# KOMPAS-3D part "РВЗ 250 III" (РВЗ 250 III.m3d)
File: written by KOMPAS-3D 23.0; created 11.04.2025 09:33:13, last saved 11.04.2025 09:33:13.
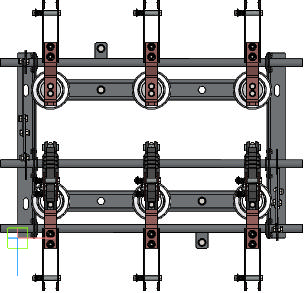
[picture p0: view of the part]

Document properties: Автор: pc; Полное имя файла: C:\Users\pc\Desktop\работа\РВЗ\3D макеты\РВЗ 250 III.m3d

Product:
- Body: Тело 1
    Масса: 0.01131
- Body: Тело 2
    Масса: 0.01131
- Body: Тело 3
    Масса: 1.849184
- Body: Тело 4
    Масса: 1.849184
- Body: Тело 5
    Масса: 0.052628
- Body: Тело 6
    Масса: 1.849184
- Part/product: РВЗ 250 III
    Масса: 5.622798

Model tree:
1. Операция без истории:1
2. Операция без истории:2
3. Операция без истории:3
4. Операция без истории:4
5. Операция без истории:5
6. Операция без истории:6
7. Поверхность без истории:1
8. Поверхность без истории:2
9. Поверхность без истории:3
10. Поверхность без истории:4
11. Поверхность без истории:5
12. Поверхность без истории:6
13. Поверхность без истории:7
14. Поверхность без истории:8
15. Поверхность без истории:9
16. Поверхность без истории:10
17. Поверхность без истории:11
18. Поверхность без истории:12
19. Поверхность без истории:13
20. Поверхность без истории:14
21. Поверхность без истории:15
22. Поверхность без истории:16
23. Поверхность без истории:17
24. Поверхность без истории:18
25. Поверхность без истории:19
26. Поверхность без истории:20
27. Поверхность без истории:21
28. Поверхность без истории:22
29. Поверхность без истории:23
30. Поверхность без истории:24
31. Поверхность без истории:25
32. Поверхность без истории:26
33. Поверхность без истории:27
34. Поверхность без истории:28
35. Поверхность без истории:29
36. Поверхность без истории:30
37. Поверхность без истории:31
38. Поверхность без истории:32
39. Поверхность без истории:33
40. Поверхность без истории:34
41. Поверхность без истории:35
42. Поверхность без истории:36
43. Поверхность без истории:37
44. Поверхность без истории:38
45. Поверхность без истории:39
46. Поверхность без истории:40
47. Поверхность без истории:41
48. Поверхность без истории:42
49. Поверхность без истории:43
50. Поверхность без истории:44
51. Поверхность без истории:45
52. Поверхность без истории:46
53. Поверхность без истории:47
54. Поверхность без истории:48
55. Поверхность без истории:49
56. Поверхность без истории:50
57. Поверхность без истории:51
58. Поверхность без истории:52
59. Поверхность без истории:53
60. Поверхность без истории:54
61. Поверхность без истории:55
62. Поверхность без истории:56
63. Поверхность без истории:57
64. Поверхность без истории:58
65. Поверхность без истории:59
66. Поверхность без истории:60
67. Поверхность без истории:61
68. Поверхность без истории:62
69. Поверхность без истории:63
70. Поверхность без истории:64
71. Поверхность без истории:65
72. Поверхность без истории:66
73. Поверхность без истории:67
74. Поверхность без истории:68
75. Поверхность без истории:69
76. Поверхность без истории:70
77. Поверхность без истории:71
78. Поверхность без истории:72
79. Поверхность без истории:73
80. Поверхность без истории:74
81. Поверхность без истории:75
82. Поверхность без истории:76
83. Поверхность без истории:77
84. Поверхность без истории:78
85. Поверхность без истории:79
86. Поверхность без истории:80
87. Поверхность без истории:81
88. Поверхность без истории:82
89. Поверхность без истории:83
90. Поверхность без истории:84
91. Поверхность без истории:85
92. Поверхность без истории:86
93. Поверхность без истории:87
94. Поверхность без истории:88
95. Поверхность без истории:89
96. Поверхность без истории:90
97. Поверхность без истории:91
98. Поверхность без истории:92
99. Поверхность без истории:93
100. Поверхность без истории:94
101. Поверхность без истории:95
102. Поверхность без истории:96
103. Поверхность без истории:97
104. Поверхность без истории:98
105. Поверхность без истории:99
106. Поверхность без истории:100
107. Поверхность без истории:101
108. Поверхность без истории:102
109. Поверхность без истории:103
110. Поверхность без истории:104
111. Поверхность без истории:105
112. Поверхность без истории:106
113. Поверхность без истории:107
114. Поверхность без истории:108
115. Поверхность без истории:109
116. Поверхность без истории:110
117. Поверхность без истории:111
118. Поверхность без истории:112
119. Поверхность без истории:113
120. Поверхность без истории:114
121. Поверхность без истории:115
122. Поверхность без истории:116
123. Поверхность без истории:117
124. Поверхность без истории:118
125. Поверхность без истории:119
126. Поверхность без истории:120
127. Поверхность без истории:121
128. Поверхность без истории:122
129. Поверхность без истории:123
130. Поверхность без истории:124
131. Поверхность без истории:125
132. Поверхность без истории:126
133. Поверхность без истории:127
134. Поверхность без истории:128
135. Поверхность без истории:129
136. Поверхность без истории:130
137. Поверхность без истории:131
138. Поверхность без истории:132
139. Поверхность без истории:133
140. Поверхность без истории:134
141. Поверхность без истории:135
142. Поверхность без истории:136
143. Поверхность без истории:137
144. Поверхность без истории:138
145. Поверхность без истории:139
146. Поверхность без истории:140
147. Поверхность без истории:141
148. Поверхность без истории:142
149. Поверхность без истории:143
150. Поверхность без истории:144
151. Поверхность без истории:145
152. Поверхность без истории:146
153. Поверхность без истории:147
154. Поверхность без истории:148
155. Поверхность без истории:149
156. Поверхность без истории:150
157. Поверхность без истории:151
158. Поверхность без истории:152
159. Поверхность без истории:153
160. Поверхность без истории:154
161. Поверхность без истории:155
162. Поверхность без истории:156
163. Поверхность без истории:157
164. Поверхность без истории:158
165. Поверхность без истории:159
166. Поверхность без истории:160
167. Поверхность без истории:161
168. Поверхность без истории:162
169. Поверхность без истории:163
170. Поверхность без истории:164
171. Поверхность без истории:165
172. Поверхность без истории:166
173. Поверхность без истории:167
174. Поверхность без истории:168
175. Поверхность без истории:169
176. Поверхность без истории:170
177. Поверхность без истории:171
178. Поверхность без истории:172
179. Поверхность без истории:173
180. Поверхность без истории:174
181. Поверхность без истории:175
182. Поверхность без истории:176
183. Поверхность без истории:177
184. Поверхность без истории:178
185. Поверхность без истории:179
186. Поверхность без истории:180
187. Поверхность без истории:181
188. Поверхность без истории:182
189. Поверхность без истории:183
190. Поверхность без истории:184
191. Поверхность без истории:185
192. Поверхность без истории:186
193. Поверхность без истории:187
194. Поверхность без истории:188
195. Поверхность без истории:189
196. Поверхность без истории:190
197. Поверхность без истории:191
198. Поверхность без истории:192
199. Поверхность без истории:193
200. Поверхность без истории:194
201. Поверхность без истории:195
202. Поверхность без истории:196
203. Поверхность без истории:197
204. Поверхность без истории:198
205. Поверхность без истории:199
206. Поверхность без истории:200
207. Поверхность без истории:201
208. Поверхность без истории:202
209. Поверхность без истории:203
210. Поверхность без истории:204
211. Поверхность без истории:205
212. Поверхность без истории:206
213. Поверхность без истории:207
214. Поверхность без истории:208
215. Поверхность без истории:209
216. Поверхность без истории:210
217. Поверхность без истории:211
218. Поверхность без истории:212
219. Поверхность без истории:213
220. Поверхность без истории:214
221. Поверхность без истории:215
222. Поверхность без истории:216
223. Поверхность без истории:217
224. Поверхность без истории:218
225. Поверхность без истории:219
226. Поверхность без истории:220
227. Поверхность без истории:221
228. Поверхность без истории:222
229. Поверхность без истории:223
230. Поверхность без истории:224
231. Поверхность без истории:225
232. Поверхность без истории:226
233. Поверхность без истории:227
234. Поверхность без истории:228
235. Поверхность без истории:229
236. Поверхность без истории:230
237. Поверхность без истории:231
238. Поверхность без истории:232
239. Поверхность без истории:233
240. Поверхность без истории:234
241. Поверхность без истории:235
242. Поверхность без истории:236
243. Поверхность без истории:237
244. Поверхность без истории:238
245. Поверхность без истории:239
246. Поверхность без истории:240
247. Поверхность без истории:241
248. Поверхность без истории:242
249. Поверхность без истории:243
250. Поверхность без истории:244
251. Поверхность без истории:245
252. Поверхность без истории:246
253. Поверхность без истории:247
254. Поверхность без истории:248
255. Поверхность без истории:249
256. Поверхность без истории:250
257. Поверхность без истории:251
258. Поверхность без истории:252
259. Поверхность без истории:253
260. Поверхность без истории:254
261. Поверхность без истории:255
262. Поверхность без истории:256
263. Поверхность без истории:257
264. Поверхность без истории:258
265. Поверхность без истории:259
266. Поверхность без истории:260
267. Поверхность без истории:261
268. Поверхность без истории:262
269. Поверхность без истории:263
270. Поверхность без истории:264
271. Поверхность без истории:265
272. Поверхность без истории:266
273. Поверхность без истории:267
274. Поверхность без истории:268
275. Поверхность без истории:269
276. Поверхность без истории:270
277. Поверхность без истории:271
278. Поверхность без истории:272
279. Поверхность без истории:273
280. Поверхность без истории:274
281. Поверхность без истории:275
282. Поверхность без истории:276
283. Поверхность без истории:277
284. Поверхность без истории:278
285. Поверхность без истории:279
286. Поверхность без истории:280
287. Поверхность без истории:281
288. Поверхность без истории:282
289. Поверхность без истории:283
290. Поверхность без истории:284
291. Поверхность без истории:285
292. Поверхность без истории:286
293. Поверхность без истории:287
294. Поверхность без истории:288
295. Поверхность без истории:289
296. Поверхность без истории:290
297. Поверхность без истории:291
298. Поверхность без истории:292
299. Поверхность без истории:293
300. Поверхность без истории:294
301. Поверхность без истории:295
302. Поверхность без истории:296
303. Поверхность без истории:297
304. Поверхность без истории:298
305. Поверхность без истории:299
306. Поверхность без истории:300
307. Поверхность без истории:301
308. Поверхность без истории:302
309. Поверхность без истории:303
310. Поверхность без истории:304
311. Поверхность без истории:305
312. Поверхность без истории:306
313. Поверхность без истории:307
314. Поверхность без истории:308
315. Поверхность без истории:309
316. Поверхность без истории:310
317. Поверхность без истории:311
318. Поверхность без истории:312
319. Поверхность без истории:313
320. Поверхность без истории:314
321. Поверхность без истории:315
322. Поверхность без истории:316
323. Поверхность без истории:317
324. Поверхность без истории:318
325. Поверхность без истории:319
326. Поверхность без истории:320
327. Поверхность без истории:321
328. Поверхность без истории:322
329. Поверхность без истории:323
330. Поверхность без истории:324
331. Поверхность без истории:325
332. Поверхность без истории:326
333. Поверхность без истории:327
334. Поверхность без истории:328
335. Поверхность без истории:329
336. Поверхность без истории:330
337. Поверхность без истории:331
338. Поверхность без истории:332
339. Поверхность без истории:333
340. Поверхность без истории:334
341. Поверхность без истории:335
342. Поверхность без истории:336
343. Поверхность без истории:337
344. Поверхность без истории:338
345. Поверхность без истории:339
346. Поверхность без истории:340
347. Поверхность без истории:341
348. Поверхность без истории:342
349. Поверхность без истории:343
350. Поверхность без истории:344
351. Поверхность без истории:345
352. Поверхность без истории:346
353. Поверхность без истории:347
354. Поверхность без истории:348
355. Поверхность без истории:349
356. Поверхность без истории:350
357. Поверхность без истории:351
358. Поверхность без истории:352
359. Поверхность без истории:353
360. Поверхность без истории:354
361. Поверхность без истории:355
362. Поверхность без истории:356
363. Поверхность без истории:357
364. Поверхность без истории:358
365. Поверхность без истории:359
366. Поверхность без истории:360
367. Поверхность без истории:361
368. Поверхность без истории:362
369. Поверхность без истории:363
370. Поверхность без истории:364
371. Поверхность без истории:365
372. Поверхность без истории:366
373. Поверхность без истории:367
374. Поверхность без истории:368
375. Поверхность без истории:369
376. Поверхность без истории:370
377. Поверхность без истории:371
378. Поверхность без истории:372
379. Поверхность без истории:373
